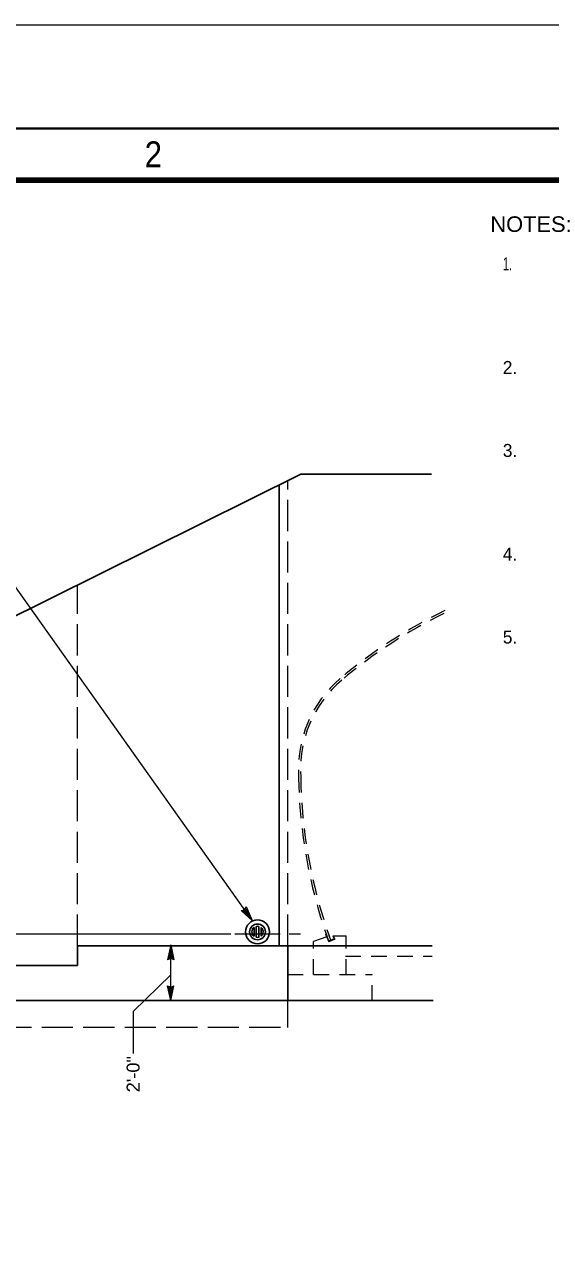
# Model space of a CAD drawing. Extents: x -22.3 to 19.7, y -11.8 to 18.2.
# Drawn here: x 5.45 to 10.52, y 6.25 to 18.16 of the extents above; entities that cross this region are included whole.
import ezdxf
from ezdxf.enums import TextEntityAlignment as Align

# ---------------------------------------------------------------- set-up
doc = ezdxf.new("R2010")
doc.units = 0
doc.header["$LTSCALE"] = 0.05
doc.linetypes.add('LONG_DASHED', pattern=[7.5, 6, -1.5])
doc.linetypes.add('MEDIUM_DASHED', pattern=[4.5, 3, -1.5])
doc.layers.add('1', color=7, linetype='Continuous', lineweight=13)

msp = doc.modelspace()

# ---------------------------------------------------------------- linework, layer by layer
at = {"layer": '1'}
for p, q in [((7.64658, 9.51631), (4.31458, 14.21531)), ((7.64658, 9.51631), (7.58858, 9.65131)), ((7.64658, 9.51631), (7.53758, 9.61631)), ((7.55458, 9.61131), (7.57558, 9.61631)), ((7.62558, 9.54631), (7.55458, 9.61131)), ((7.57058, 9.60631), (7.58058, 9.60931)), ((7.60458, 9.57631), (7.57058, 9.60631)), ((7.57558, 9.61631), (7.58758, 9.63431)), ((7.58058, 9.60931), (7.58558, 9.61731)), ((7.60458, 9.57631), (7.58558, 9.61731)), ((7.62558, 9.54631), (7.58758, 9.63431)), ((4.91658, 9.39231), (7.43958, 9.39231)), ((7.47558, 9.39231), (7.91458, 9.39231)), ((7.99958, 9.39231), (8.10958, 9.39231)), ((6.85858, 9.28531), (6.82758, 9.14131)), ((6.85858, 9.24831), (6.83858, 9.15431)), ((6.85858, 9.21231), (6.84958, 9.16731)), ((6.85858, 9.17131), (6.84958, 9.16731)), ((6.85858, 8.74831), (6.85858, 9.28531)), ((6.85858, 9.28531), (6.88958, 9.14131)), ((6.85858, 9.24831), (6.87858, 9.15431)), ((6.85858, 9.21231), (6.86858, 9.16731)), ((6.86858, 9.16731), (6.85858, 9.17131)), ((6.85858, 9.16331), (6.83858, 9.15431)), ((6.87858, 9.15431), (6.85858, 9.16331)), ((6.85858, 8.99631), (6.49658, 8.64431)), ((6.85858, 8.74831), (6.82758, 8.89231)), ((6.85858, 8.78531), (6.83858, 8.87931)), ((6.83858, 8.87931), (6.85858, 8.87031)), ((6.85858, 8.82131), (6.84858, 8.86631)), ((6.84858, 8.86631), (6.85858, 8.86231)), ((6.85858, 8.74831), (6.88958, 8.89231)), ((6.85858, 8.78531), (6.87858, 8.87931)), ((6.85858, 8.87031), (6.87858, 8.87931)), ((6.85858, 8.82131), (6.86758, 8.86631)), ((6.85858, 8.86231), (6.86758, 8.86631)), ((6.49658, 8.64431), (6.49658, 8.23831))]:
    msp.add_line(p, q, dxfattribs=at)
at = {"layer": '1', "lineweight": 25}
for p, q in [((7.90458, 9.27731), (7.90458, 13.72331)), ((7.66358, 9.36831), (7.66358, 9.45331)), ((7.68158, 9.35931), (7.68158, 9.46331)), ((7.70858, 9.35831), (7.70858, 9.46331)), ((7.73058, 9.36831), (7.73058, 9.45331)), ((7.98658, 9.27731), (7.98658, 8.74831)), ((5.21558, 9.08631), (5.96158, 9.08631)), ((5.21558, 8.74831), (9.38858, 8.74831))]:
    msp.add_line(p, q, dxfattribs=at)
at = {"layer": '1', "linetype": 'LONG_DASHED'}
for p, q in [((7.98658, 9.27731), (7.98658, 13.76531)), ((5.96158, 9.27731), (5.96158, 12.75531)), ((7.98458, 8.74831), (7.98458, 8.49031)), ((5.21558, 8.49131), (7.98458, 8.49131))]:
    msp.add_line(p, q, dxfattribs=at)
at = {"layer": '1', "linetype": 'MEDIUM_DASHED'}
for p, q in [((8.36258, 9.36331), (8.23658, 9.31831)), ((8.23658, 8.99931), (8.23658, 9.31831)), ((8.35158, 9.38931), (8.35458, 9.39031)), ((8.35158, 9.38931), (8.38258, 9.31631)), ((8.35458, 9.39031), (8.38458, 9.32131)), ((8.44058, 9.34131), (8.38258, 9.31631)), ((8.38458, 9.37531), (8.40358, 9.32931)), ((8.42258, 9.37231), (8.42558, 9.37431)), ((8.42558, 9.37431), (8.44058, 9.34131)), ((8.42558, 9.37431), (8.54958, 9.37431)), ((8.54958, 8.99931), (8.54958, 9.37431)), ((8.54258, 9.17731), (9.38058, 9.17731)), ((7.98658, 8.74831), (7.98658, 8.99931)), ((7.98658, 8.99931), (8.79958, 8.99931)), ((8.79958, 8.74831), (8.79958, 8.99931)), ((7.98658, 8.74831), (8.79958, 8.74831))]:
    msp.add_line(p, q, dxfattribs=at)
at = {"layer": '1'}
for points in [[(-22.30942, 18.16031), (19.69058, 18.16031), (19.69058, -11.83969)], [(7.53758, 9.61631), (7.57158, 9.62231), (7.58858, 9.65131)], [(6.88958, 9.14131), (6.85858, 9.15531), (6.82758, 9.14131)], [(6.82758, 8.89231), (6.85858, 8.87831), (6.88958, 8.89231)]]:
    msp.add_lwpolyline(points, dxfattribs=at)
at = {"layer": '1', "lineweight": 40}
msp.add_lwpolyline([(-21.30942, -10.83969), (-21.30942, 17.16031), (18.69058, 17.16031), (18.69058, -10.83969)], close=True, dxfattribs=at)
at = {"layer": '1', "lineweight": 90}
msp.add_lwpolyline([(-19.80942, 16.66031), (18.19058, 16.66031), (18.19058, -10.33969), (-19.80942, -10.33969)], close=True, dxfattribs=at)
at = {"layer": '1', "lineweight": 25}
for points in [[(5.21558, 12.38531), (8.11158, 13.82531), (9.37358, 13.82531)], [(5.96158, 9.08631), (5.96158, 9.27731), (9.38058, 9.27731)]]:
    msp.add_lwpolyline(points, dxfattribs=at)
at = {"layer": '1', "linetype": 'MEDIUM_DASHED'}
msp.add_lwpolyline([(8.42258, 9.37231), (8.43458, 9.34331), (8.38458, 9.32131)], dxfattribs=at)
at = {"layer": '1', "lineweight": 25}
for radius in [0.11574, 0.07571]:
    msp.add_circle((7.69558, 9.41131), radius, dxfattribs=at)
at = {"layer": '1', "linetype": 'MEDIUM_DASHED'}
for centre, radius, start, end in [((11.6334, 8.12581), 4.87482, 115.92373, 130.09764), ((11.6334, 8.12581), 4.85409, 116.17053, 130.09764), ((9.2376, 10.97993), 1.14838, 130.38466, 183.72825), ((9.2376, 10.97993), 1.12773, 130.38466, 183.72825), ((12.96571, 10.97993), 4.87492, 180.86487, 199.33073), ((12.96571, 10.97993), 4.85419, 180.86487, 199.33073)]:
    msp.add_arc(centre, radius, start, end, dxfattribs=at)
at = {"layer": '1', "lineweight": 25}
for start, end in [(126.02737, 233.1301), (75.96376, 104.03624), (309.80557, 48.81408), (254.93151, 282.75753)]:
    msp.add_arc((7.69558, 9.41131), 0.05401, start, end, dxfattribs=at)

# ---------------------------------------------------------------- texts
at = {"layer": '1', "width": 0.9}
msp.add_text('2', height=0.25, dxfattribs=at).set_placement((6.69108, 16.78531), align=Align.CENTER)
at = {"layer": '1'}
for s, height, width, p in [('NOTES:', 0.15, 1.05, (9.94025, 16.16198)), ('1.', 0.125, 0.65, (10.06025, 15.79198))]:
    msp.add_text(s, height=height, dxfattribs=dict(at, width=width)).set_placement(p)
for s, p in [('2.', (10.06025, 14.79198)), ('3.', (10.06025, 13.99198)), ('4.', (10.06025, 12.99198)), ('5.', (10.06025, 12.19198))]:
    msp.add_text(s, height=0.125, dxfattribs=at).set_placement(p)
at = {"layer": '1', "width": 1.05}
msp.add_text('2\'-0"', height=0.125, rotation=90, dxfattribs=at).set_placement((6.55858, 8.21331), align=Align.RIGHT)

doc.saveas('drawing.dxf')
